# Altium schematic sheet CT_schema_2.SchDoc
size 350 x 214 mm
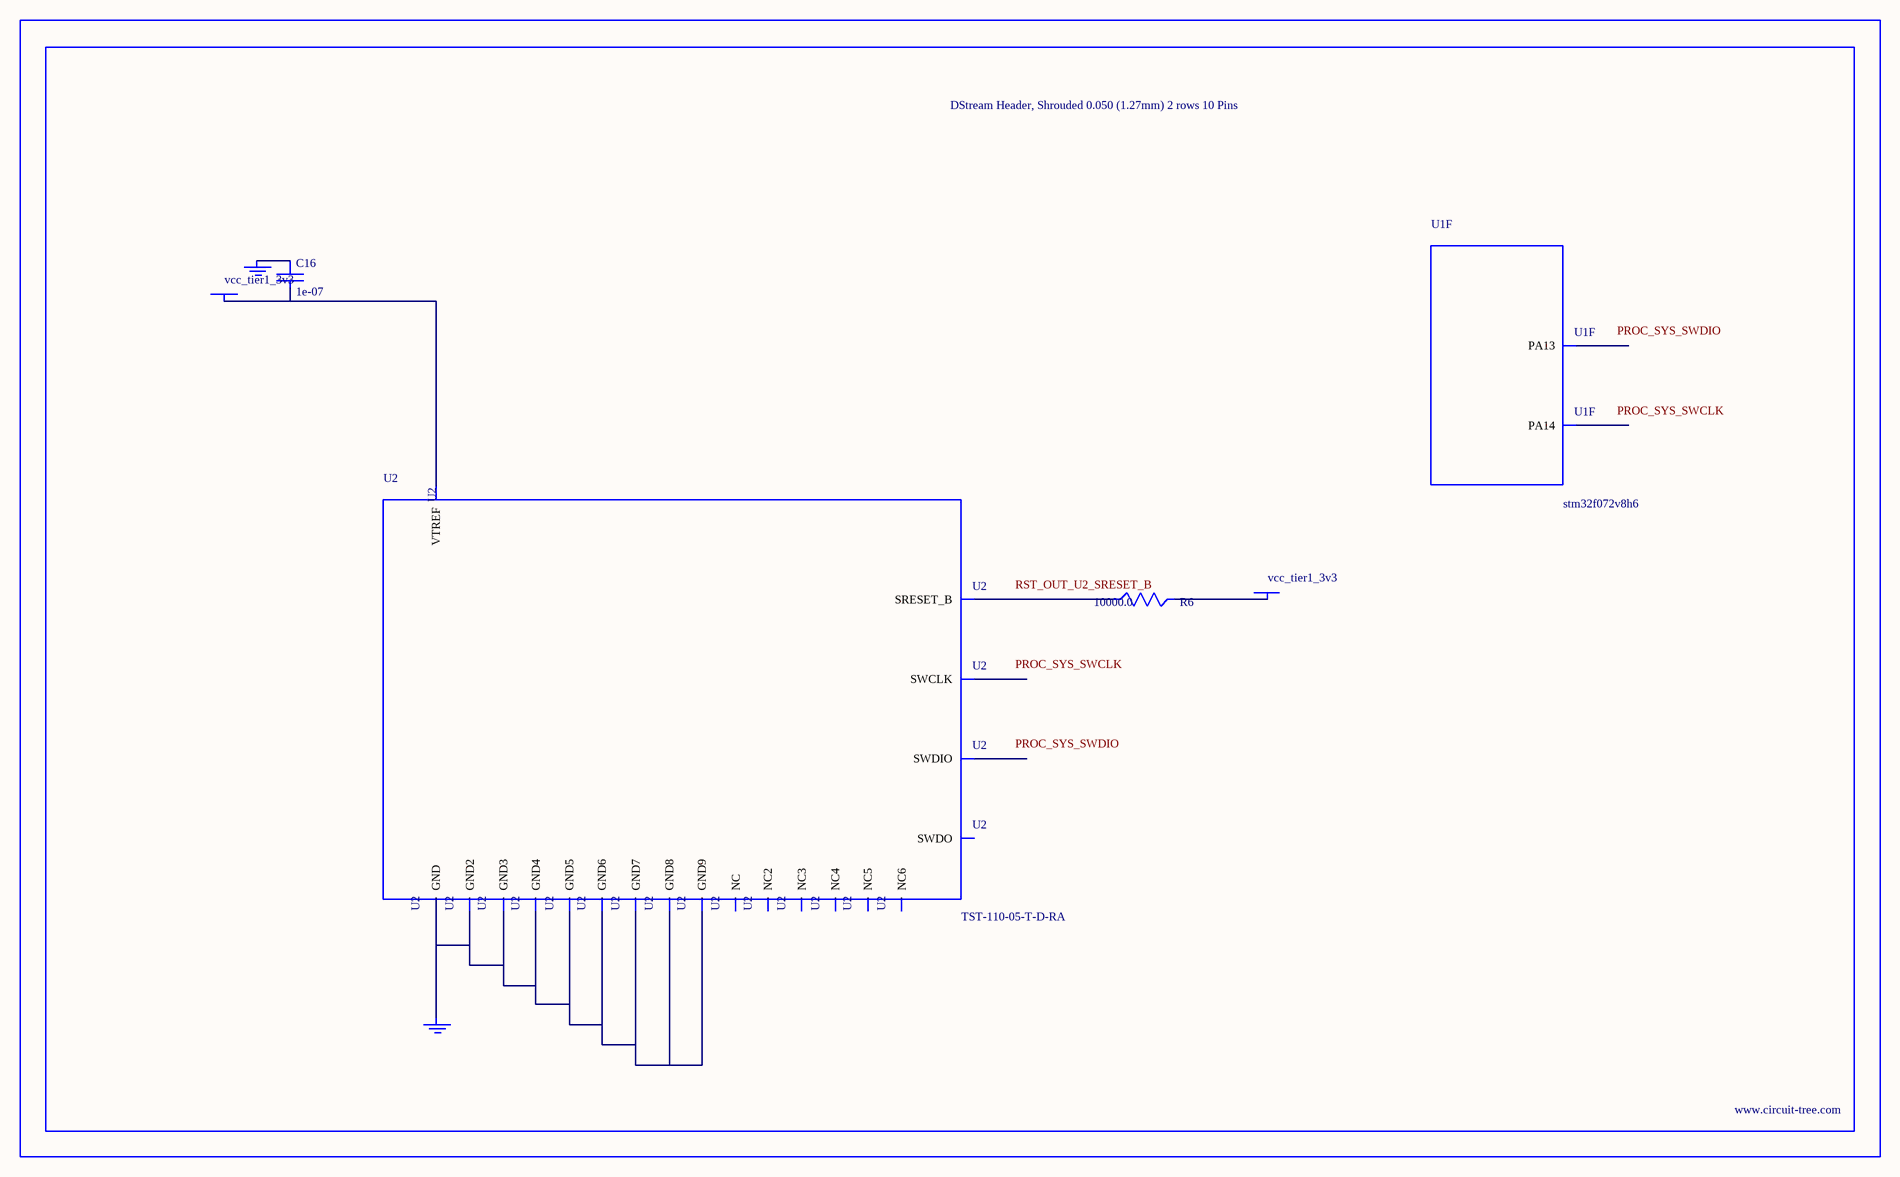
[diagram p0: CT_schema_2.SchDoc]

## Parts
BORDER1  (no value)
C16  1e-07  [C0402]
GND_INSTANCE_1_0  (no value)
GND_INSTANCE_1_1  (no value)
POWER_INSTANCE_1_0  vcc_tier1_3v3
POWER_INSTANCE_1_1  vcc_tier1_3v3
R6  10000.0  [R0603]
U1  stm32f072v8h6  [UFBGA100]  (part F of 10)
U2  TST-110-05-T-D-RA  [TST-110-05-T-D-RA]

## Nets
NetC16_1: C16.1 GND_INSTANCE_1_0.0(GND)
NetC16_2: C16.2 POWER_INSTANCE_1_0.0(PWR) U2.1(VTREF)
NetGND_INSTANCE_1_1_0: GND_INSTANCE_1_1.0(GND) U2.4(GND) U2.6(GND2) U2.8(GND3) U2.10(GND4) U2.12(GND5) U2.14(GND6) U2.16(GND7) U2.18(GND8) U2.20(GND9)
NetPOWER_INSTANCE_1_1_0: POWER_INSTANCE_1_1.0(PWR) R6.2
NetR6_1: R6.1 U2.15(SRESET_B)

Not connected (* = marked no-connect by the designer): U1 A10(PA14) A11(PA13); U2 2(NC) 3(NC2) 5(NC3) 7(SWDIO) 9(SWCLK) 11(NC4) 13(SWDO) 17(NC5) 19(NC6)

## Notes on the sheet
- Labels drawn without touching a wire or pin: PROC_SYS_SWCLK, PROC_SYS_SWDIO, RST_OUT_U2_SRESET_B

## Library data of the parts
BORDER1 = BORDER_PAGE1
C16 = C0402C104K3RACTU
GND_INSTANCE_1_0 GND_INSTANCE_1_1 = GND
POWER_INSTANCE_1_0 POWER_INSTANCE_1_1 = PWR
R6 = RC0603JR-0710KL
